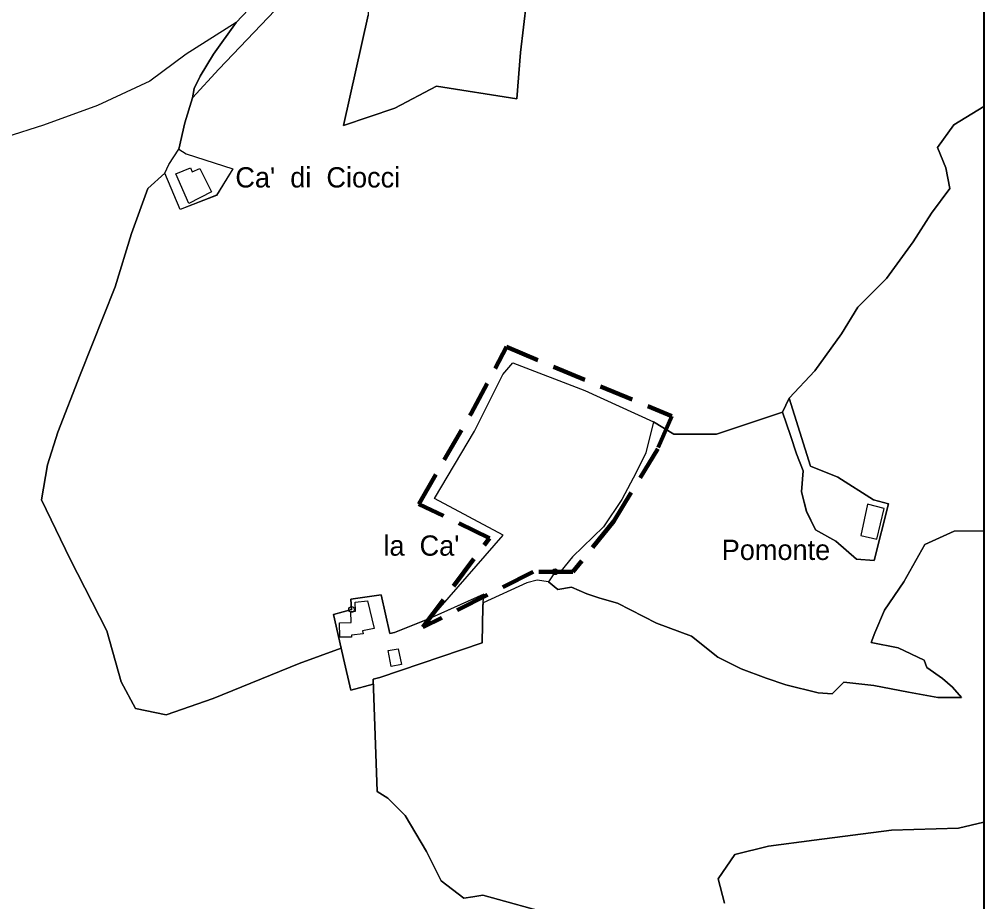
# Model space of a CAD drawing. Extents: x 650468 to 655025, y 889970 to 891591.
# Drawn here: x 654549.5 to 655025.2, y 890511.8 to 890947 of the extents above; entities that cross this region are included whole.
import ezdxf
from ezdxf.enums import TextEntityAlignment as Align

# ---------------------------------------------------------------- set-up
doc = ezdxf.new("R2010")
doc.units = 0
doc.header["$LTSCALE"] = 5.6
doc.header["$PDMODE"] = 32
doc.header["$PDSIZE"] = 2.8
doc.linetypes.add('MEDIUM_DASHED', pattern=[4.5, 3, -1.5])
for name, color, linetype, lineweight in [('12', 7, 'Continuous', 25), ('2', 7, 'Continuous', 25), ('35', 7, 'Continuous', 25), ('36', 7, 'Continuous', 25), ('37', 7, 'Continuous', 25), ('61', 7, 'Continuous', 35), ('7', 7, 'MEDIUM_DASHED', 100)]:
    doc.layers.add(name, color=color, linetype=linetype, lineweight=lineweight)
doc.layers.add('60', color=7, linetype='Continuous')

msp = doc.modelspace()

# ---------------------------------------------------------------- linework, layer by layer
at = {"layer": '12'}
for points in [[(654787.94, 890771.78), (654792.95, 890777.67), (654828.36, 890763.88), (654862.31, 890748.43), (654858.6, 890733.15), (654853.8, 890723.55), (654846.61, 890710.24), (654837.66, 890696.71), (654822.4, 890681.87)], [(654752.57, 890651.85), (654788.16, 890692.56), (654754.35, 890710.67), (654773.98, 890743.84), (654787.94, 890771.78)], [(654822.4, 890681.87), (654816.67, 890674.92), (654816.67, 890674.92), (654813.74, 890674.55), (654813.74, 890674.55), (654813.74, 890674.55), (654813.74, 890674.55), (654810.54, 890669.57), (654804.89, 890670.42), (654799.86, 890669.07), (654778.23, 890659.27), (654778.57, 890663.55), (654752.57, 890651.85)]]:
    msp.add_lwpolyline(points, dxfattribs=at)
at = {"layer": '2'}
for points in [[(654628.75, 890853.2), (654621.19, 890871.09), (654623.17, 890875.36), (654628.17, 890882.95), (654631.74, 890880.71), (654654.73, 890873.21), (654646.73, 890860.2)], [(654626.7, 890870.73), (654633.9, 890873.73), (654634.82, 890871.79), (654638.51, 890873.42), (654644.24, 890861.96), (654633.09, 890856.17)], [(654929.27, 890760.15), (654925.97, 890753.25), (654929.89, 890741.78), (654932.91, 890732.73), (654936.22, 890724.28), (654935.32, 890714.02), (654937.73, 890704.36), (654942.25, 890695.31), (654952.2, 890689.58), (654962.45, 890680.83), (654971.24, 890680.14), (654978.27, 890708.03), (654970.77, 890710.04), (654953.25, 890721.15), (654939.76, 890726.65)], [(654967.83, 890707.88), (654964.52, 890692.49), (654972.43, 890690.61), (654976.02, 890705.78)], [(654715.17, 890659.56), (654721.31, 890660.18), (654724.59, 890646.56), (654718.83, 890645.47), (654719.05, 890644.01), (654713.3, 890643.28), (654713.37, 890642.26), (654707.55, 890642.26), (654707.4, 890649.35), (654713.16, 890649.54), (654712.94, 890655.01), (654715.27, 890655.15)], [(654731.36, 890635.78), (654736.4, 890636.54), (654738.02, 890628.76), (654732.88, 890627.84)]]:
    msp.add_lwpolyline(points, close=True, dxfattribs=at)
for points in [[(654704.53, 890653.46), (654708.27, 890636.85), (654709.37, 890631.85), (654713.07, 890616.15), (654724.07, 890619.15), (654724.07, 890621.55), (654727.27, 890622.45), (654777.87, 890639.55), (654778.07, 890657.35), (654778.57, 890663.55), (654771.67, 890660.45), (654752.57, 890651.85), (654734.57, 890644.65), (654732.27, 890644.05), (654728.04, 890663.17), (654713.01, 890660.98), (654713.38, 890655.97)], [(654713.38, 890655.97), (654709.2, 890654.78), (654704.53, 890653.46)]]:
    msp.add_lwpolyline(points, dxfattribs=at)
msp.add_point((654713.38, 890655.97), dxfattribs=at)
at = {"layer": '35'}
msp.add_lwpolyline([(654614.69, 890954.07), (654630.14, 890964.31), (654692.09, 890985.03), (654685.79, 890974.85), (654668.7, 890958.56), (654656.4, 890945.47), (654631.8, 890929.74), (654613.87, 890916.44), (654587.96, 890904.47), (654561.39, 890894.84), (654542.79, 890888.85), (654523.19, 890882.21)], dxfattribs=at)
at = {"layer": '36'}
for points in [[(654685.79, 890974.85), (654678.29, 890967.87), (654668.7, 890958.56), (654656.4, 890945.47), (654645.3, 890929.76), (654638.71, 890919), (654635.71, 890912.89), (654634.86, 890908.35), (654647.96, 890922.47), (654675.69, 890951.44), (654721.52, 890969.55), (654721.52, 890949.03), (654709.46, 890894.71), (654734.78, 890903.16), (654755.28, 890914.02), (654794.86, 890907.77), (654796.64, 890930.61), (654799.73, 890955.61), (654801.79, 890976.62), (654809.01, 890984.62), (654846.38, 891017.87)], [(654897.31, 890511.18), (654894.22, 890523.18), (654902.47, 890535.18), (654918.96, 890539.18), (654941.64, 890542.18), (654979.79, 890547.18), (655012.78, 890548.18), (655025.2, 890551.04), (655025.2, 890694.71), (655010.61, 890694.56), (654996.17, 890688.06), (654985.86, 890669.56), (654976.3, 890655.67), (654971.48, 890644.5), (654969.67, 890639.67), (654982.93, 890636.96), (654995.9, 890630.92), (654997.1, 890627.3), (655004.94, 890621.87), (655009.76, 890617.64), (655014.29, 890612.51), (655002.53, 890612.51)], [(654810.54, 890669.57), (654804.89, 890670.42), (654799.86, 890669.07), (654778.23, 890659.27), (654778.07, 890657.35), (654777.87, 890639.55), (654727.27, 890622.45), (654724.07, 890621.55)], [(655002.53, 890612.51), (654988.06, 890615.23), (654970.93, 890618.54), (654956.18, 890620.04), (654954.37, 890618.23), (654950.45, 890614.31), (654943.52, 890614.91), (654927.54, 890618.83), (654917.89, 890622.15), (654905.53, 890626.68), (654894.08, 890632.41), (654881.02, 890642.82), (654863.83, 890649.15), (654844.54, 890659.11), (654835.91, 890661.51), (654829.47, 890663.64), (654821.93, 890666.96), (654815.04, 890665.78), (654810.54, 890669.57)], [(654724.07, 890621.54), (654726.05, 890566.19), (654731.3, 890562.9), (654739.84, 890554.35), (654750.35, 890536.6), (654757.58, 890522.13), (654768.75, 890513.58)], [(654768.75, 890513.58), (654773.17, 890514.32), (654778.17, 890515), (654813.81, 890505.18)]]:
    msp.add_lwpolyline(points, dxfattribs=at)
at = {"layer": '37'}
msp.add_line((654579.57, 890771.68), (654568.47, 890743.4), dxfattribs=at)
for points in [[(654990.35, 890837.32), (654999.43, 890851.46), (655008.52, 890863.58), (655006.5, 890873.68), (655002.46, 890883.77), (655010.54, 890894.88), (655025.2, 890903.97), (655025.2, 891015.9)], [(654675.69, 890951.44), (654647.96, 890922.47), (654634.86, 890908.35), (654631.04, 890895.9), (654628.17, 890882.94), (654631.74, 890880.7), (654654.73, 890873.2), (654646.73, 890860.19), (654628.75, 890853.19), (654621.19, 890871.08)], [(654799.73, 890955.61), (654796.64, 890930.61), (654794.86, 890907.77), (654755.28, 890914.02), (654734.78, 890903.16), (654709.46, 890894.71), (654721.52, 890949.03)], [(654656.4, 890945.47), (654631.8, 890929.74), (654613.87, 890916.44), (654587.96, 890904.47), (654561.39, 890894.84), (654542.79, 890888.85), (654523.19, 890882.21)], [(654628.17, 890882.94), (654631.04, 890895.9), (654634.86, 890908.35), (654635.71, 890912.89), (654638.71, 890919), (654645.3, 890929.76), (654656.4, 890945.47)], [(654634.86, 890908.35), (654631.04, 890895.9), (654628.17, 890882.94)], [(654813.74, 890674.54), (654810.54, 890669.57), (654815.04, 890665.78), (654821.93, 890666.96), (654829.47, 890663.64), (654835.91, 890661.51), (654844.54, 890659.11), (654863.83, 890649.15), (654881.02, 890642.82), (654894.08, 890632.41), (654905.53, 890626.68), (654917.89, 890622.15), (654927.54, 890618.83), (654943.52, 890614.91), (654950.45, 890614.31), (654954.37, 890618.23), (654956.18, 890620.04), (654970.93, 890618.54), (654988.06, 890615.23), (655002.53, 890612.51), (655014.29, 890612.51), (655009.76, 890617.64), (655004.94, 890621.87), (654997.1, 890627.3), (654995.9, 890630.92), (654982.93, 890636.96), (654969.67, 890639.67), (654971.48, 890644.5), (654976.3, 890655.67), (654985.86, 890669.56), (654996.17, 890688.06), (655010.61, 890694.56), (655025.2, 890694.71), (655025.2, 890903.97)], [(655025.2, 890903.97), (655010.54, 890894.88), (655002.46, 890883.77), (655006.5, 890873.68), (655008.52, 890863.58), (654999.43, 890851.46), (654990.35, 890837.32), (654977.23, 890819.14), (654963.1, 890805), (654955.03, 890791.88), (654941.9, 890773.7), (654929.27, 890760.14), (654939.76, 890726.64), (654953.25, 890721.14), (654970.77, 890710.03), (654978.27, 890708.02), (654971.24, 890680.13), (654962.45, 890680.82), (654952.2, 890689.57), (654942.25, 890695.3), (654937.73, 890704.35), (654935.32, 890714.01), (654936.22, 890724.27), (654932.91, 890732.72), (654929.89, 890741.77), (654925.97, 890753.24)], [(654929.27, 890760.14), (654941.9, 890773.7), (654955.03, 890791.88), (654963.1, 890805), (654977.23, 890819.14), (654990.35, 890837.32), (654999.43, 890851.46), (655008.52, 890863.58), (655006.5, 890873.68), (655002.46, 890883.77), (655010.54, 890894.88), (655025.2, 890903.97)], [(654708.27, 890636.84), (654687.56, 890629.29), (654645.17, 890612.12), (654621.96, 890604.04), (654606.82, 890607.07), (654599.76, 890620.2), (654592.69, 890645.45), (654574.52, 890680.79), (654560.39, 890710.08), (654563.42, 890727.25), (654568.47, 890743.4), (654579.57, 890771.68), (654596.73, 890815.11), (654604.8, 890841.36), (654612.88, 890863.58), (654621.19, 890871.08), (654623.17, 890875.35), (654628.17, 890882.94)], [(654621.19, 890871.08), (654612.88, 890863.58), (654604.8, 890841.36), (654596.73, 890815.11), (654579.57, 890771.68)], [(654963.1, 890805), (654977.23, 890819.14), (654990.35, 890837.32)], [(654929.27, 890760.14), (654941.9, 890773.7), (654955.03, 890791.88), (654963.1, 890805)], [(654787.94, 890771.77), (654792.95, 890777.66), (654828.36, 890763.87), (654862.31, 890748.42)], [(654752.57, 890651.84), (654788.16, 890692.55), (654754.35, 890710.66), (654773.98, 890743.83), (654787.94, 890771.77)], [(654862.31, 890748.42), (654872.26, 890742.39), (654893.46, 890742.39), (654911.63, 890748.45), (654925.97, 890753.24), (654929.27, 890760.14)], [(654862.31, 890748.42), (654872.26, 890742.39), (654893.46, 890742.39), (654911.63, 890748.45), (654925.97, 890753.24)], [(654925.97, 890753.24), (654911.63, 890748.45), (654893.46, 890742.39), (654872.26, 890742.39), (654862.31, 890748.42)], [(654862.31, 890748.42), (654858.6, 890733.14), (654853.8, 890723.54), (654846.61, 890710.23), (654837.66, 890696.7), (654822.4, 890681.86)], [(654568.47, 890743.4), (654563.42, 890727.25), (654560.39, 890710.08)], [(654560.39, 890710.08), (654574.52, 890680.79), (654592.69, 890645.45), (654599.76, 890620.2)], [(654822.4, 890681.86), (654816.67, 890674.91), (654816.67, 890674.91), (654813.74, 890674.54), (654813.74, 890674.54), (654813.74, 890674.54), (654813.74, 890674.54)], [(654713.38, 890655.96), (654713.01, 890660.97), (654728.04, 890663.16), (654732.27, 890644.04), (654734.57, 890644.64), (654752.57, 890651.84)], [(654645.17, 890612.12), (654687.56, 890629.29), (654708.27, 890636.84), (654704.53, 890653.45), (654709.2, 890654.77), (654713.38, 890655.96)], [(654724.07, 890621.54), (654724.07, 890619.14), (654713.07, 890616.14), (654709.37, 890631.84), (654708.27, 890636.84)], [(654599.76, 890620.2), (654606.82, 890607.07), (654621.96, 890604.04), (654645.17, 890612.12)], [(654813.81, 890505.18), (654778.17, 890515), (654773.17, 890514.32), (654768.75, 890513.58), (654757.58, 890522.13), (654750.35, 890536.6), (654739.84, 890554.35), (654731.3, 890562.9), (654726.05, 890566.19), (654724.07, 890621.54)], [(655025.2, 890361.65), (655025.2, 890551.04), (655012.78, 890548.18), (654979.79, 890547.18), (654941.64, 890542.18), (654918.96, 890539.18), (654902.47, 890535.18), (654894.22, 890523.18), (654897.31, 890511.18)]]:
    msp.add_lwpolyline(points, dxfattribs=at)
for p in [(654813.74, 890674.54), (654713.38, 890655.96)]:
    msp.add_point(p, dxfattribs=at)
at = {"layer": '61', "lineweight": 40}
msp.add_lwpolyline([(653618.27, 891591.08), (655025.2, 891591.08), (655025.2, 889969.62), (653618.27, 889969.62)], close=True, dxfattribs=at)
at = {"layer": '7'}
msp.add_lwpolyline([(654789.76, 890785.42), (654871.38, 890751.22), (654864.4, 890735.17), (654842.78, 890699.57), (654822.55, 890674.44), (654803.02, 890674.44), (654748.6, 890647.22), (654781.39, 890691.19), (654746.51, 890707.94), (654772.32, 890752.62)], close=True, dxfattribs=at)

# ---------------------------------------------------------------- texts
at = {"layer": '60'}
for s, p in [("Ca'  di  Ciocci", (654696.7, 890864.06)), ("la  Ca'", (654747.83, 890682.47)), ('Pomonte', (654922.72, 890680.37))]:
    msp.add_text(s, height=10, dxfattribs=at).set_placement(p, align=Align.CENTER)

doc.saveas('drawing.dxf')
